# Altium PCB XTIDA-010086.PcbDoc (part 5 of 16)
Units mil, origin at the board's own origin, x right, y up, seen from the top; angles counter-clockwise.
Board outline 14763.78 x 8267.72 mil, 6 copper layers (Top Layer, GND Layer, Signal Layer 1, Signal Layer 2, Power Layer, Bottom Layer), stack 62 mil thick; 1933 components, 1002 nets, 4886 pads, 6482 vias.
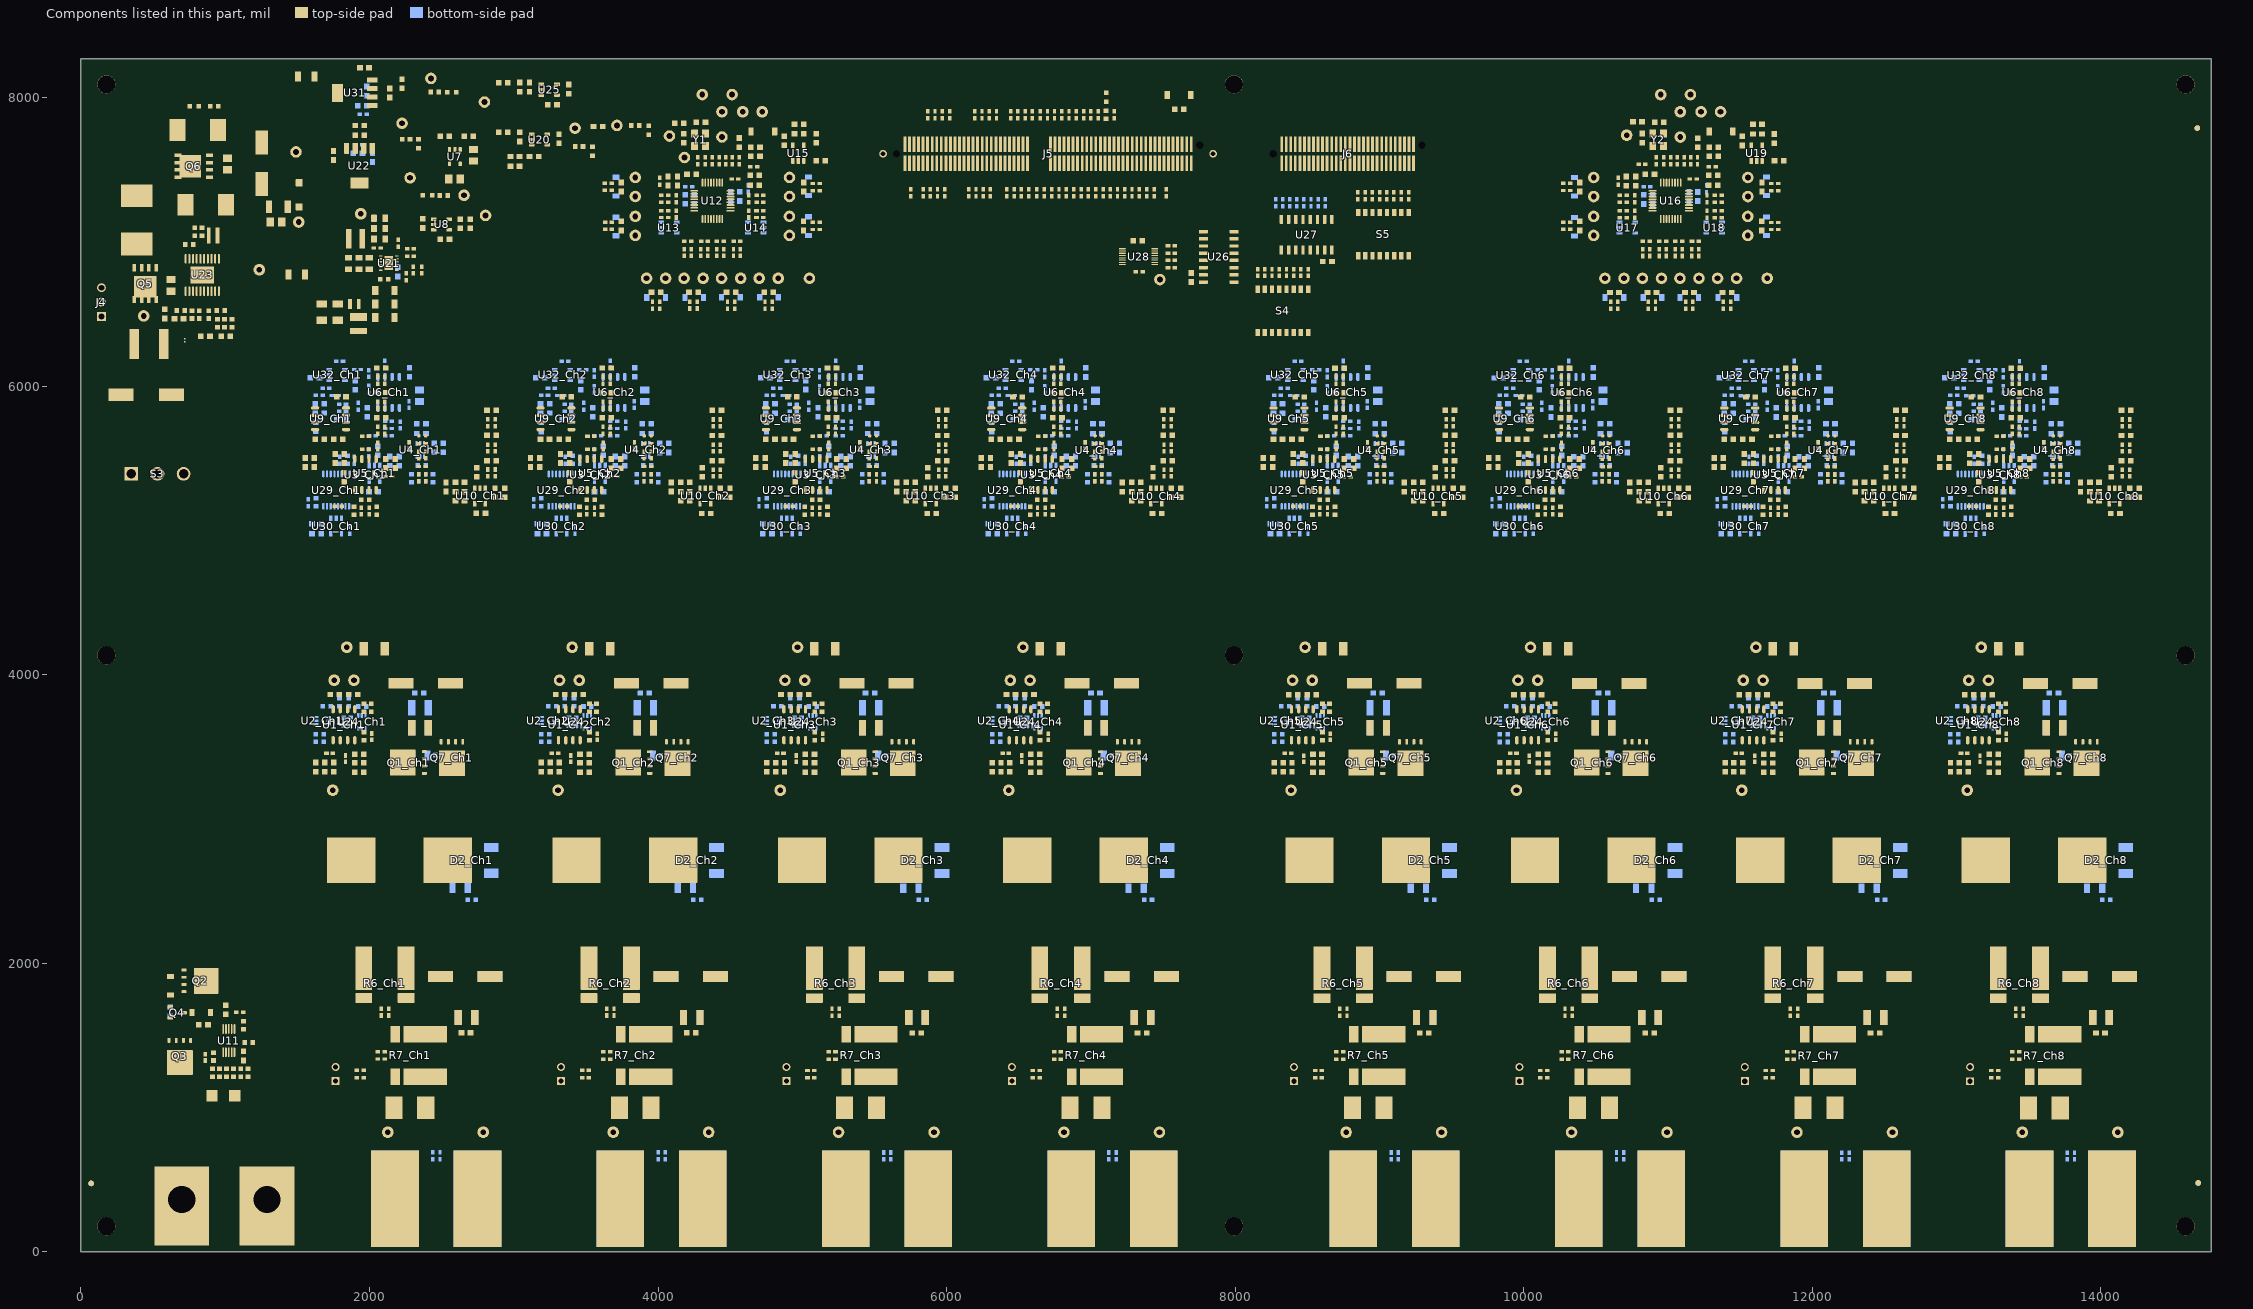
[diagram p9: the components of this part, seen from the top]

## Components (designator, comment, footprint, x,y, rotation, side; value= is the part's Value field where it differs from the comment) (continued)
U6_Ch7 "TLV2171IDR" D0008A_N 11898.7,5955.57 r90 bottom (schematic designator U6)
U6_Ch8 "TLV2171IDR" D0008A_N 13460.7,5955.5 r90 bottom (schematic designator U6)
U7 "LP5907MFX-2.5/NOPB" DBV0005A_L 2592,7589.32 r270 top
U8 "TPS72325DBVT" DBV0005A_N 2500,7119.7 r0 top
U9_Ch1 "LM393AD" D0008A_N 1731,5773.55 r180 top (schematic designator U9)
U9_Ch2 "LM393AD" D0008A_N 3293,5773.47 r180 top (schematic designator U9)
U9_Ch3 "LM393AD" D0008A_N 4855,5773.39 r180 top (schematic designator U9)
U9_Ch4 "LM393AD" D0008A_N 6417,5773.31 r180 top (schematic designator U9)
U9_Ch5 "LM393AD" D0008A_N 8372.7,5773.24 r180 top (schematic designator U9)
U9_Ch6 "LM393AD" D0008A_N 9934.7,5773.16 r180 top (schematic designator U9)
U9_Ch7 "LM393AD" D0008A_N 11496.7,5773.08 r180 top (schematic designator U9)
U9_Ch8 "LM393AD" D0008A_N 13058.7,5773 r180 top (schematic designator U9)
U10_Ch1 "TLV171IDBVR" DBV0005A_N 2766.54,5238.3 r270 top (schematic designator U10)
U10_Ch2 "TLV171IDBVR" DBV0005A_N 4328.54,5238.22 r270 top (schematic designator U10)
U10_Ch3 "TLV171IDBVR" DBV0005A_N 5890.54,5238.14 r270 top (schematic designator U10)
U10_Ch4 "TLV171IDBVR" DBV0005A_N 7452.54,5238.06 r270 top (schematic designator U10)
U10_Ch5 "TLV171IDBVR" DBV0005A_N 9408.24,5237.98 r270 top (schematic designator U10)
U10_Ch6 "TLV171IDBVR" DBV0005A_N 10970.24,5237.91 r270 top (schematic designator U10)
U10_Ch7 "TLV171IDBVR" DBV0005A_N 12532.24,5237.83 r270 top (schematic designator U10)
U10_Ch8 "TLV171IDBVR" DBV0005A_N 14094.24,5237.75 r270 top (schematic designator U10)
U11 "LM5060MM/NOPB" MUB10A_N 1025.33,1463.77 r90 top
U12 "ADS131M08IPBSR" PBS0032A_N 4377.11,7284.01 r90 top
U13 "ESDS304DBVR" DBV0005A_N 4076,7098.7 r0 bottom
U14 "ESDS304DBVR" DBV0005A_N 4677.29,7098.7 r180 bottom
U15 "REF2025DBV" DBV0005A_N 4972.33,7614.48 r90 top
U16 "ADS131M08IPBSR" PBS0032A_N 11018.82,7283.7 r90 top
U17 "ESDS304DBVR" DBV0005A_N 10717.7,7098.39 r0 bottom
U18 "ESDS304DBVR" DBV0005A_N 11318.99,7098.39 r180 bottom
U19 "REF2025DBV" DBV0005A_N 11614.03,7614.16 r90 top
U20 "LP5907MFX-3.3/NOPB" DBV0005A_N 3178.03,7708.4 r0 top
U21 "TPS63710DRR" DRR0012C 2134,6851.98 r180 top
U22 "LP38693MP-5.0/NOPB" NDC0005A_N 1931,7527.15 r270 top
U23 "LM5118MH/NOPB" MXA20A_N 841.5,6769.7 r90 top
U24_Ch1 "SN74LVC1G11DCKR" DCK0006A_N 1947.59,3673.33 r90 bottom (schematic designator U24)
U24_Ch2 "SN74LVC1G11DCKR" DCK0006A_N 3509.59,3673.25 r90 bottom (schematic designator U24)
U24_Ch3 "SN74LVC1G11DCKR" DCK0006A_N 5071.59,3673.17 r90 bottom (schematic designator U24)
U24_Ch4 "SN74LVC1G11DCKR" DCK0006A_N 6633.59,3673.09 r90 bottom (schematic designator U24)
U24_Ch5 "SN74LVC1G11DCKR" DCK0006A_N 8589.29,3673.01 r90 bottom (schematic designator U24)
U24_Ch6 "SN74LVC1G11DCKR" DCK0006A_N 10151.29,3672.93 r90 bottom (schematic designator U24)
U24_Ch7 "SN74LVC1G11DCKR" DCK0006A_N 11713.29,3672.86 r90 bottom (schematic designator U24)
U24_Ch8 "SN74LVC1G11DCKR" DCK0006A_N 13275.29,3672.78 r90 bottom (schematic designator U24)
U25 "TPS73633DBVR" DBV0005A_N 3245.53,8054 r0 top
U26 "SN74HC148DR" D0016A-MFG 7885.79,6895.7 r180 top
U27 "SN74HC148DR" D0016A-MFG 8495.2,7048.97 r270 top
U28 "SN74LV163ADGVR" DGV0016A_L 7330.2,6896.39 r0 top
U29_Ch1 "CD4053BPWR" PW0016A_L 1770,5279 r270 bottom (schematic designator U29)
U29_Ch2 "CD4053BPWR" PW0016A_L 3332,5278.92 r270 bottom (schematic designator U29)
U29_Ch3 "CD4053BPWR" PW0016A_L 4894,5278.84 r270 bottom (schematic designator U29)
U29_Ch4 "CD4053BPWR" PW0016A_L 6456,5278.76 r270 bottom (schematic designator U29)
U29_Ch5 "CD4053BPWR" PW0016A_L 8411.7,5278.69 r270 bottom (schematic designator U29)
U29_Ch6 "CD4053BPWR" PW0016A_L 9973.7,5278.61 r270 bottom (schematic designator U29)
U29_Ch7 "CD4053BPWR" PW0016A_L 11535.7,5278.53 r270 bottom (schematic designator U29)
U29_Ch8 "CD4053BPWR" PW0016A_L 13097.7,5278.45 r270 bottom (schematic designator U29)
U30_Ch1 "TLV1701AIDBVR" DBV0005A_N 1769,5030 r270 bottom (schematic designator U30)
U30_Ch2 "TLV1701AIDBVR" DBV0005A_N 3331,5029.92 r270 bottom (schematic designator U30)
U30_Ch3 "TLV1701AIDBVR" DBV0005A_N 4893,5029.84 r270 bottom (schematic designator U30)
U30_Ch4 "TLV1701AIDBVR" DBV0005A_N 6455,5029.76 r270 bottom (schematic designator U30)
U30_Ch5 "TLV1701AIDBVR" DBV0005A_N 8410.7,5029.69 r270 bottom (schematic designator U30)
U30_Ch6 "TLV1701AIDBVR" DBV0005A_N 9972.7,5029.61 r270 bottom (schematic designator U30)
U30_Ch7 "TLV1701AIDBVR" DBV0005A_N 11534.7,5029.53 r270 bottom (schematic designator U30)
U30_Ch8 "TLV1701AIDBVR" DBV0005A_N 13096.7,5029.45 r270 bottom (schematic designator U30)
U31 "LP38693MP-5.0/NOPB" NDC0005A_N 1899,8032 r180 top
U32_Ch1 "TLV171IDBVR" DBV0005A_N 1776,6077.24 r0 bottom (schematic designator U32)
U32_Ch2 "TLV171IDBVR" DBV0005A_N 3338.24,6076.91 r0 bottom (schematic designator U32)
U32_Ch3 "TLV171IDBVR" DBV0005A_N 4898.35,6077.31 r0 bottom (schematic designator U32)
U32_Ch4 "TLV171IDBVR" DBV0005A_N 6462.24,6076.76 r0 bottom (schematic designator U32)
U32_Ch5 "TLV171IDBVR" DBV0005A_N 8417.94,6076.68 r0 bottom (schematic designator U32)
U32_Ch6 "TLV171IDBVR" DBV0005A_N 9980.7,6075.84 r0 bottom (schematic designator U32)
U32_Ch7 "TLV171IDBVR" DBV0005A_N 11541.94,6076.52 r0 bottom (schematic designator U32)
U32_Ch8 "TLV171IDBVR" DBV0005A_N 13103.94,6076.44 r0 bottom (schematic designator U32)
Y1 "SIT8924BA-22-33E-8.192000G" SiTime_SiT8924B_2 4291.11,7706.01 r0 top
Y2 "SIT8924BA-22-33E-8.192000G" SiTime_SiT8924B_2 10931.82,7706.7 r0 top
ZZ1 "This Assembly Note is for PCB labels only" AssemblyNoteLabel 467,9160 r0 top
ZZ2 "These assemblies are ESD sensitive, ESD precautions shall be observed." AssemblyNote 468,9090 r0 top
ZZ3 "These assemblies must be clean and free from flux and all contaminants. Use of no clean flux is not acceptable." AssemblyNote 469,9025 r0 top
ZZ4 "These assemblies must comply with workmanship standards IPC-A-610 Class 2, unless otherwise specified." AssemblyNote 470,8958 r0 top

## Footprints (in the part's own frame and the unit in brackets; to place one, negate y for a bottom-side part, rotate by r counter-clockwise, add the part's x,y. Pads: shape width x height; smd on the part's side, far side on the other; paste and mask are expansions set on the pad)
0402 [mm] "0402 from SM-752 data"
  rect 0.8x0.6 smd: 1(-0.6,0) 2(0.6,0)
  silkscreen extent -1.22,-0.52 1.22,0.52, body extent -0.55,-0.3 0.55,0.3, height 0.6
0603 [mm] "0603 from SM-752 data"
  rect 1x0.95 smd: 1(-0.8,0) 2(0.8,0)
  silkscreen extent -1.52,-0.69 1.52,0.69, body extent -0.87,-0.47 0.87,0.47, height 1
0603_HV [mil] "Ernesto recommended land pattern.  26 mil between pads."
  rect 30x30 smd: 1(-28,0) 2(28,0)
  silkscreen extent -52,-24 52,24, body extent -34,-19 34,19, height 39
0603L [mm] "0603 from SM-752 data"
  rect 0.8x0.85 smd: 1(-0.7,0) 2(0.7,0)
  silkscreen extent -0.07,-0.33 0.07,0.33, body extent -0.87,-0.47 0.87,0.47, height 1
0612 [mm] "Panasonic recommended land pattern, fb97d03ed01.pdf dated April 2008"
  rect 0.65x2.75 smd: 1(-0.775,0) 2(0.775,0)
  silkscreen extent -1.1,-1.9 1.1,1.9, body extent -0.9,-1.7 0.9,1.7, height 0.85
0805_HV [mil] "0805 with 30mil clearance between pads"
  rect 50x63 smd: 1(-40,0) 2(40,0)
  silkscreen extent -74,-40 74,40, body extent -43,-29 43,29, height 57
0805_HV1 [mm] "Custom footprint based on analyzing multiple manufacturer recommendations"
  rrect10% 1x1.25 smd: 1(-1,0) 2(1,0)
  silkscreen extent -0.2,-0.75 0.2,0.75, body extent -1.1,-0.72 1.1,0.73, height 1.45
1206 [mm] "1206 from SM-752 data"
  rect 1.3x1.85 smd: 1(-1.45,0) 2(1.45,0)
  silkscreen extent -2.4,-1.21 2.4,1.21, body extent -1.7,-0.9 1.7,0.9, height 1.35
1206_190 [mm] "1206_190"
  rect 1.1x1.6 smd: 1(-1.7,0) 2(1.7,0)
  silkscreen extent -0.9,-1 0.9,1, body extent -1.75,-0.95 1.75,0.95, height 1.9
1206L [mm] "1206 from SM-752 data"
  rect 1.1x1.75 smd: 1(-1.35,0) 2(1.35,0)
  silkscreen extent -0.4,-0.77 0.4,0.77, body extent -1.7,-0.9 1.7,0.9, height 1.35
1210_270 [mm] "1210"
  rect 1.3x2.7 smd: 1(-1.45,0) 2(1.45,0)
  silkscreen extent -2.32,-1.57 2.32,1.57, body extent -1.7,-1.35 1.7,1.35, height 2.7
1210_280 [mm] "SMD, 2-Leads, Body 3.6x2.8mm, Height 2.8mm"
  rect 1.1x2.2 smd: 1(-1.65,0) 2(1.65,0)
  silkscreen extent -0.84,-1.4 0.84,1.4, body extent -1.8,-1.4 1.8,1.4, height 2.8
1806_HighSpeed [mm] "Wurth recommended land pattern"
  rrect8% 1.25x1.2 smd: 1(-2.125,0) 2(2.125,0)
  silkscreen extent -1.5,-1 1.5,1, body extent -2.25,-0.8 2.25,0.8, height 1.61
2220_250 [mm] "2220"
  rect 1.6x5.3 smd: 1(-2.6,0) 2(2.6,0)
  silkscreen extent -3.69,-2.94 3.69,2.94, body extent -2.95,-2.62 2.95,2.62, height 2.5
5108 [mm] "Keystone"
  rect 1.01x1.73 smd: 1(-1.445,0) 2(1.445,0)
  body extent -1.52,-0.85 1.52,0.85, height 0.71
6125FA [mm] "Cooper Bussman 6125FA Brick Fuses, recommended land pattern OC-2531 Rev. I 3/07"
  rect 3x4 smd: 1(-2.8,0) 2(2.8,0)
  silkscreen extent -4.57,-2.27 4.57,2.27, body extent -3.17,-1.42 3.17,1.41, height 2.84
AssemblyNote [mil] "Assembly Note"
AssemblyNoteLabel [mil] "Assembly Note for PCB Labels"
CAPSMT_62_F12 [mm] "F12, SMD, 2-Leads, Body 10.5x10.5mm, Height 12.7mm"
  rect 4.4x1.9 smd: 1(-4.35,0) 2(4.35,0)
  silkscreen extent -5.25,-5.25 5.25,5.25, body extent -5.25,-5.25 5.25,5.25, height 12.71
CAPSMT_62_HC0 [mm] "8 x 12mm:  Chemi-Con HC0"
  rect 4.2x2.2 smd: 1(-3.638,0.012) 2(3.662,0.012)
  silkscreen extent -4.24,-4.24 4.26,4.26, body extent -4.24,-4.24 4.26,4.26, height 12.5
CAPSMT_62_JA0 [mm] "10 x 10mm:  Chemi-Con JA0"
  rect 4.4x2.2 smd: 1(-4.45,0) 2(4.45,0)
  silkscreen extent -5.25,-5.25 5.25,5.25, body extent -5.25,-5.25 5.25,5.25, height 10.5
CB35-36-CY [mil] "Terminal 50A Lug"
  rect 550x380 hole 188 copper offset -45,0 paste-190: 1(0,0)
  body extent -960,-189 230,191, height 614
CE_Mark_5mm [mil] "Minimum text height for CE Mark"
  silkscreen extent -138,-98 138,98
controlCARD-120HSEC [mm] "Pads are not numbered according to Samtec datasheet."
  rect 0.5x2.724 smd: 1(-23.357,-1.678) 2(-23.357,1.722) 3(-22.557,-1.678) 4(-22.557,1.722) 5(-21.757,-1.678) 6(-21.757,1.722) 7(-20.957,-1.678) 8(-20.957,1.722) 9(-20.157,-1.678) 10(-20.157,1.722) 11(-19.357,-1.678) 12(-19.357,1.722) 13(-18.557,-1.678) 14(-18.557,1.722) 15(-17.757,-1.678) 16(-17.757,1.722) 17(-16.957,-1.678) 18(-16.957,1.722) 19(-16.157,-1.678) 20(-16.157,1.722) 21(-15.357,-1.678) 22(-15.357,1.722) 23(-14.557,-1.678) 24(-14.557,1.722) 25(-13.757,-1.678) 26(-13.757,1.722) 27(-12.957,-1.678) 28(-12.957,1.722) 29(-12.157,-1.678) 30(-12.157,1.722) 31(-11.357,-1.678) 32(-11.357,1.722) 33(-10.557,-1.678) 34(-10.557,1.722) 35(-9.757,-1.678) 36(-9.757,1.722) 37(-8.957,-1.678) 38(-8.957,1.722) 39(-8.157,-1.678) 40(-8.157,1.722) 41(-7.357,-1.678) 42(-7.357,1.722) 43(-6.557,-1.678) 44(-6.557,1.722) 45(-5.757,-1.678) 46(-5.757,1.722) 47(-4.957,-1.678) 48(-4.957,1.722) 49(-4.157,-1.678) 50(-4.157,1.722) 51(-3.357,-1.678) 52(-3.357,1.722) 53(-2.557,-1.678) 54(-2.557,1.722) 55(-1.757,-1.678) 56(-1.757,1.722) 57(2.243,-1.678) 58(2.243,1.722) 59(3.043,-1.678) 60(3.043,1.722) 61(3.843,-1.678) 62(3.843,1.722) 63(4.643,-1.678) 64(4.643,1.722) 65(5.443,-1.678) 66(5.443,1.722) 67(6.243,-1.678) 68(6.243,1.722) 69(7.043,-1.678) 70(7.043,1.722) 71(7.843,-1.678) 72(7.843,1.722) 73(8.643,-1.678) 74(8.643,1.722) 75(9.443,-1.678) 76(9.443,1.722) 77(10.243,-1.678) 78(10.243,1.722) 79(11.043,-1.678) 80(11.043,1.722) 81(11.843,-1.678) 82(11.843,1.722) 83(12.643,-1.678) 84(12.643,1.722) 85(13.443,-1.678) 86(13.443,1.722) 87(14.243,-1.678) 88(14.243,1.722) 89(15.043,-1.678) 90(15.043,1.722) 91(15.843,-1.678) 92(15.843,1.722) 93(16.643,-1.678) 94(16.643,1.722) 95(17.443,-1.678) 96(17.443,1.722) 97(18.243,-1.678) 98(18.243,1.722) 99(19.043,-1.678) 100(19.043,1.722) 101(19.843,-1.678) 102(19.843,1.722) 103(20.643,-1.678) 104(20.643,1.722) 105(21.443,-1.678) 106(21.443,1.722) 107(22.243,-1.678) 108(22.243,1.722) 109(23.043,-1.678) 110(23.043,1.722) 111(23.843,-1.678) 112(23.843,1.722) 113(24.643,-1.678) 114(24.643,1.722) 115(25.443,-1.678) 116(25.443,1.722) 117(26.243,-1.678) 118(26.243,1.722) 119(27.043,-1.678) 120(27.043,1.722)
  round 0.025 hole 1.27 unplated mask+0.876: 181(-24.857,0.022) 182(28.543,1.522)
  round 1.348 hole 0.84: 185(-27.207,0.022) 186(30.893,0.022)
  silkscreen extent -32.11,-3.86 35.8,3.9, body extent -31.75,-3.48 35.3,3.52, height 12.35
controlCARD-180HSEC-60pinAddon [mm] "Pads are not numbered according to datasheet."
  round 0.025 hole 1.27 unplated mask+0.876: 61(-13.1,0) 62(13.1,1.5)
  rect 0.5x2.724 smd: 121(-11.6,-1.7) 122(-11.6,1.7) 123(-10.8,-1.7) 124(-10.8,1.7) 125(-10,-1.7) 126(-10,1.7) 127(-9.2,-1.7) 128(-9.2,1.7) 129(-8.4,-1.7) 130(-8.4,1.7) 131(-7.6,-1.7) 132(-7.6,1.7) 133(-6.8,-1.7) 134(-6.8,1.7) 135(-6,-1.7) 136(-6,1.7) 137(-5.2,-1.7) 138(-5.2,1.7) 139(-4.4,-1.7) 140(-4.4,1.7) 141(-3.6,-1.7) 142(-3.6,1.7) 143(-2.8,-1.7) 144(-2.8,1.7) 145(-2,-1.7) 146(-2,1.7) 147(-1.2,-1.7) 148(-1.2,1.7) 149(-0.4,-1.7) 150(-0.4,1.7) 151(0.4,-1.7) 152(0.4,1.7) 153(1.2,-1.7) 154(1.2,1.7) 155(2,-1.7) 156(2,1.7) 157(2.8,-1.7) 158(2.8,1.7) 159(3.6,-1.7) 160(3.6,1.7) 161(4.4,-1.7) 162(4.4,1.7) 163(5.2,-1.7) 164(5.2,1.7) 165(6,-1.7) 166(6,1.7) 167(6.8,-1.7) 168(6.8,1.7) 169(7.6,-1.7) 170(7.6,1.7) 171(8.4,-1.7) 172(8.4,1.7) 173(9.2,-1.7) 174(9.2,1.7) 175(10,-1.7) 176(10,1.7) 177(10.8,-1.7) 178(10.8,1.7) 179(11.6,-1.7) 180(11.6,1.7)
  silkscreen extent -14.68,-3.88 14.68,3.88, body extent -14.3,-3.5 14.3,3.5, height 7.95
CSM3637Z [mm] "SMD, 4-Leads, Body 9.398x9.144mm"
  rrect3% 7.62x2.95 smd: 1(-1.145,3.735) 2(-1.145,-3.735)
  rrect6% 1.68x2.95 smd: 3(4.115,3.735) 4(4.115,-3.735)
  silkscreen extent -4.83,-1.9 4.83,1.9, body extent -4.83,-4.7 4.83,4.7, height 0.89
D0008A_N [mm] "SOIC, 8-Leads, Body 4.9x3.9mm, Pitch 1.27mm, IPC Medium Density"
  oval 1.45x0.6 smd: 1(-2.725,1.905) 2(-2.725,0.635) 3(-2.725,-0.635) 4(-2.725,-1.905) 5(2.725,-1.905) 6(2.725,-0.635) 7(2.725,0.635) 8(2.725,1.905)
  silkscreen extent -3.3,-2.5 0.9,2.5, body extent -3,-2.45 3,2.45, height 1.63
D0016A-MFG [mm]
  rrect17% 1.55x0.6 smd paste-1000 mask+0: 1(-2.7,4.445) 2(-2.7,3.175) 3(-2.7,1.905) 4(-2.7,0.635) 5(-2.7,-0.635) 6(-2.7,-1.905) 7(-2.7,-3.175) 8(-2.7,-4.445) 9(2.7,-4.445) 10(2.7,-3.175) 11(2.7,-1.905) 12(2.7,-0.635) 13(2.7,0.635) 14(2.7,1.905) 15(2.7,3.175) 16(2.7,4.445)
  silkscreen extent -4.18,-5 1.55,5, body extent -3,-4.95 3,4.95, height 1.75
DBV0005A_L [mm] "SOT23, 5-Leads, Body 2.9x1.6mm, Pitch 0.95mm, Lead Span 2.8mm, IPC High Density"
  rrect18% 0.8x0.55 smd: 1(-1.275,0.95) 2(-1.275,0) 3(-1.275,-0.95) 4(1.275,-0.95) 5(1.275,0.95)
  silkscreen extent -0.35,-1.55 0.35,1.55, body extent -1.42,-1.46 1.42,1.46, height 1.09
DBV0005A_N [mm] "SOT23, 5-Leads, Body 2.9x1.6mm, Pitch 0.95mm, Lead Span 2.8mm, IPC Medium Density"
  rrect17% 1x0.6 smd: 1(-1.375,0.95) 2(-1.375,0) 3(-1.375,-0.95) 4(1.375,-0.95) 5(1.375,0.95)
  silkscreen extent -0.25,-1.55 0.25,1.55, body extent -1.42,-1.46 1.42,1.46, height 1.09
DCK0006A_N [mm] "SOT23, 6-Leads, Body 2x1.3mm, Pitch 0.65mm, Lead Span 2.1mm, IPC Medium Density"
  rrect25% 0.85x0.4 smd: 1(-1.125,0.65) 2(-1.125,0) 3(-1.125,-0.65) 4(1.125,-0.65) 5(1.125,0) 6(1.125,0.65)
  silkscreen extent -1.5,-1.09 0.51,1.09, body extent -1.14,-1 1.14,1, height 0.95
DGV0016A_L [mm] "TSSOP, 16-Leads, Body 3.6x4.4mm, Pitch 0.4mm, IPC High Density"
  oval 1.2x0.2 smd: 1(-2.85,1.4) 2(-2.85,1) 3(-2.85,0.6) 4(-2.85,0.2) 5(-2.85,-0.2) 6(-2.85,-0.6) 7(-2.85,-1) 8(-2.85,-1.4) 9(2.85,-1.4) 10(2.85,-1) 11(2.85,-0.6) 12(2.85,-0.2) 13(2.85,0.2) 14(2.85,0.6) 15(2.85,1) 16(2.85,1.4)
  silkscreen extent -3.32,-1.85 1.85,1.85, body extent -3.21,-1.8 3.21,1.8, height 1.2
DNK0008A [mm] "SON, 8-Leads, Body 5x6mm"
  rrect39% 0.86x0.51 smd paste-0.05 mask-0.05: 1(-2.82,1.905) 2(-2.82,0.635) 3(-2.82,-0.635) 4(-2.82,-1.905) 5(2.82,-1.905) 6(2.82,-0.635) 7(2.82,0.635) 8(2.82,1.905)
  rrect8% 1.48x1.27 on Top Paste: 9(-0.18,-1.47) 9(-0.18,0) 9(-0.18,1.47) 9(1.5,-1.47) 9(1.5,0) 9(1.5,1.47)
  rrect5% 4.34x4.6 smd paste-3 mask-0.05: 9(1.08,0)
  silkscreen extent -3.2,-2.7 3.2,2.7, body extent -3.05,-2.55 3.05,2.55, height 1.06
DPAK [mm] "D-PAK, 3-Pads, Body 6.22x6.73mm (max), TO-252AA using nominal STEP model"
  rrect6% 2.6x1.6 smd: 1(-3.4,2.28) 3(-3.4,-2.28)
  rrect2% 6.2x5.8 smd paste-2.9: 4(3.4,0)
  silkscreen extent -4.5,-3.3 4.7,3.28, body extent -3.86,-3.29 5.84,3.29, height 2.48
DQJ0008A [mm] "SMD, 8-Leads, Body 5.75x4.9mm"
  rrect39% 0.91x0.51 smd paste-0.05 mask-0.05: 1(-2.795,1.905) 2(-2.795,0.635) 3(-2.795,-0.635) 4(-2.795,-1.905) 5(2.795,-1.905) 6(2.795,-0.635) 7(2.795,0.635) 8(2.795,1.905)
  rrect8% 1.58x1.25 on Top Paste: 9(-0.38,1.45) 9(-0.38,0) 9(-0.38,-1.45) 9(1.4,1.45) 9(1.4,0) 9(1.4,-1.45)
  rrect3% 3.48x4.47 on Top Solder: 9(0.55,0)
  rrect2% 4.49x4.57 smd paste-2.5 mask-2.5: 9(1.005,0)
  silkscreen extent -3,-2.6 3,2.6, body extent -3.13,-2.45 3.13,2.45, height 1.15
DRR0012C [mm] "SON, 12-Leads, Body 3x3mm, Pitch 0.5mm, Thermal Pad 1.5x2.5mm"
  rrect40% 0.6x0.25 smd: 1(-1.4,1.25) 2(-1.4,0.75) 3(-1.4,0.25) 4(-1.4,-0.25) 5(-1.4,-0.75) 6(-1.4,-1.25) 7(1.4,-1.25) 8(1.4,-0.75) 9(1.4,-0.25) 10(1.4,0.25) 11(1.4,0.75) 12(1.4,1.25)
  rrect9% 1.38x1.11 on Top Paste: 13(0,0.66) 13(0,-0.66)
  rrect7% 1.5x2.5 smd paste-1.7: 13(0,0)
  silkscreen extent -1.6,-1.65 1.6,1.65, body extent -1.55,-1.55 1.55,1.55, height 0.81
ESD_Overlay_Medium [mil]
  silkscreen extent -127,-109 125,110
F95_B [mm] "AVX F95 series, size B"
  rect 1.4x3 smd: 1(-1.25,0)
  rect 1.1x3 smd: 2(1.2,0)
  silkscreen extent -0.33,-1.73 1.25,1.73, body extent -2.03,-1.5 1.67,1.5, height 2
FCC_disclaimer [mil]
Fiducial10-20 [mm]
  round 1 smd mask+0.5: 1(0,0)
  Top Layer keep-out circle w1.178: c0,0 r0.5
FP-CB25-18-CY_CONN_TERM_LUG_25MM4_7MM9-MFG [mil]
  rrect1% 670x330 smd paste+0 mask+0: 1(175,0)
  rrect1% 670x330 smd far side paste-39370.1 mask+0: 1(175,0)
  silkscreen extent 0,-180 525,180, body extent -164,-169 514,169, height 10
IEC_HotSurface_Small [mil]
  silkscreen extent -107,-93 107,92
JST_B2B-EH-A [mm] "Header (Shrouded), 2.5mm, 2x1, TH"
  rect 1.4x1.4 hole 0.9: 1(-1.25,0)
  round 1.4 hole 0.9: 2(1.25,0)
  silkscreen extent -4.2,-2.2 3.75,1.6, body extent -3.75,-2.2 3.75,1.6, height 6
Keystone5000 [mil] "For Keystone 500x miniature loop terminals"
  round 80 hole 40: 1(0,0)
  silkscreen extent -52,-52 52,52, body extent -49,-49 49,49, height 182
Keystone5001 [mil] "For Keystone 500x miniature loop terminals"
  round 80 hole 40: 1(0,0)
  silkscreen extent -52,-52 52,52, body extent -49,-49 49,49, height 182
Keystone5002 [mil] "For Keystone 500x miniature loop terminals"
  round 80 hole 40: 1(0,0)
  silkscreen extent -52,-52 52,52, body extent -49,-49 49,49, height 182
KEYSTONE_2205 [mil] "THREAD HEX ALUMINUM STANDOFF 4-40, F-F 1\""
  round 1 on Mech4: 0(0,0)
  body extent -148,-128 148,128, height 1001
Label_650x200 [mil] "Thermal Transfer Label"
  round 1 on Mech13: 0(0,0)
  silkscreen extent -325,-100 325,100, body extent -325,-100 325,100, height 1
MAKK2016 [mm] "Taiyo Yuden"
  rect 0.7x1.8 smd: 1(-0.75,0) 2(0.75,0)
  body extent -1.05,-0.85 1.05,0.85, height 1
Molex_0022284033 [mm] "Header, 2.54mm, 3x1, TH"
  rect 1.55x1.55 hole 1.02: 1(-2.54,0)
  round 1.55 hole 1.02: 2(0,0) 3(2.54,0)
  silkscreen extent -3.81,-1.24 3.81,1.5, body extent -3.81,-1.24 3.81,1.24, height 8.4
mss1278 [mm] "Coilcraft recommended land pattern.  Document 598-2 rev 04/04/13"
  rect 4x5.5 smd: 1(-4.25,0) 2(4.25,0)
  silkscreen extent -6.2,-6.2 6.2,6.2, body extent -6.15,-6.15 6.15,6.15, height 8.05
MUB10A_N [mm] "TSSOP, 10-Leads, Body 3x3mm, Pitch 0.5mm, IPC Medium Density"
  oval 1.7x0.3 smd: 1(-2.05,1) 2(-2.05,0.5) 3(-2.05,0) 4(-2.05,-0.5) 5(-2.05,-1) 6(2.05,-1) 7(2.05,-0.5) 8(2.05,0) 9(2.05,0.5) 10(2.05,1)
  silkscreen extent -2.17,-1.6 0.8,1.82, body extent -1.6,-1.6 1.6,1.6, height 1.09
MXA20A_N [mm] "TSOP, 20-Leads, Body 6.5x4.4mm, Pitch 0.65mm, Exposed Pad, IPC Medium Density"
  oval 1.7x0.35 smd: 1(-2.85,2.925) 2(-2.85,2.275) 3(-2.85,1.625) 4(-2.85,0.975) 5(-2.85,0.325) 6(-2.85,-0.325) 7(-2.85,-0.975) 8(-2.85,-1.625) 9(-2.85,-2.275) 10(-2.85,-2.925) 11(2.85,-2.925) 12(2.85,-2.275) 13(2.85,-1.625) 14(2.85,-0.975) 15(2.85,-0.325) 16(2.85,0.325) 17(2.85,0.975) 18(2.85,1.625) 19(2.85,2.275) 20(2.85,2.925)
  rect 3x4.2 smd: 21(0,0)
  silkscreen extent -2.97,-3.3 1.6,3.77, body extent -2.25,-3.3 2.25,3.3, height 1.1
NDC0005A_N [mm] "SOT223, 5-Leads, Body 6.7x3.71mm, Pitch 1.5mm, IPC Medium Density"
  rrect11% 1.9x0.9 smd: 1(-3.05,2.25) 2(-3.05,0.75) 3(-3.05,-0.75) 4(-3.05,-2.25)
  rrect5% 1.9x3.2 smd: 5(3.05,0)
  silkscreen extent -3.17,-3.35 1.8,3.38, body extent -3.48,-3.25 3.48,3.25, height 1.7
Net-Tie_10mil [mil] "10mil net tie, no solder mask opening, no solder paste"
  rect 10x10 smd paste-5 mask-5: 1(-10,0) 2(10,0)
  Top Layer region: -6,5 6,5 6,-5 -6,-5
"NY PMS 440 0025 PH"#1 [mm] "4-40 nylon screw and mounting hole"
  round 3.2 hole 3.2 unplated mask+0.178: 1(0,0)
  body extent -3.3,-3.3 3.3,3.3, height 2.69
"NY PMS 440 0025 PH"#2 [mm] "4-40 nylon screw and mounting hole"
  round 3.2 hole 3.2 unplated paste+0 mask+0.178: 1(0,0)
  body extent -3.3,-3.3 3.3,3.3, height 2.69
Pb-Free_Overlay_Small [mil]
  silkscreen extent -46,-46 46,46
PBS0032A_N [mm]
  oval 1.4x0.3 smd: 1(-3.2,1.75) 2(-3.2,1.25) 3(-3.2,0.75) 4(-3.2,0.25) 5(-3.2,-0.25) 6(-3.2,-0.75) 7(-3.2,-1.25) 8(-3.2,-1.75) 17(3.2,-1.75) 18(3.2,-1.25) 19(3.2,-0.75) 20(3.2,-0.25) 21(3.2,0.25) 22(3.2,0.75) 23(3.2,1.25) 24(3.2,1.75)
  oval 0.3x1.4 smd: 9(-1.75,-3.2) 10(-1.25,-3.2) 11(-0.75,-3.2) 12(-0.25,-3.2) 13(0.25,-3.2) 14(0.75,-3.2) 15(1.25,-3.2) 16(1.75,-3.2) 25(1.75,3.2) 26(1.25,3.2) 27(0.75,3.2) 28(0.25,3.2) 29(-0.25,3.2) 30(-0.75,3.2) 31(-1.25,3.2) 32(-1.75,3.2)
  silkscreen extent -3.6,-2.53 2.53,2.53, body extent -3.5,-3.5 3.5,3.5, height 1.12
PowerPAK_SO-8 [mil] "Vishay PowerPAK SO-8, Body 5.3x6.0mm (max), Pitch 1.27mm, IPC Medium Density"
  rect 50x24 smd mask+2.99: 1(-109.5,75) 2(-109.5,25) 3(-109.5,-25) 4(-109.5,-75)
  rect 48x24 smd mask+2.99: 5(109.5,-75) 8(109.5,75)
  rect 48x24 smd paste-12 mask+2.99: 6(109.5,-25) 7(109.5,25)
  rect 150x154 smd paste-75 mask+2.99: 9(22.5,0)
  silkscreen extent -130,-104 59,104, body extent -121,-102 121,102, height 43
PW0016A_L [mm] "TSOP, 16-Leads, Body 5x4.4mm, Pitch 0.65mm, IPC High Density"
  oval 1.2x0.4 smd: 1(-2.85,2.275) 2(-2.85,1.625) 3(-2.85,0.975) 4(-2.85,0.325) 5(-2.85,-0.325) 6(-2.85,-0.975) 7(-2.85,-1.625) 8(-2.85,-2.275) 9(2.85,-2.275) 10(2.85,-1.625) 11(2.85,-0.975) 12(2.85,-0.325) 13(2.85,0.325) 14(2.85,0.975) 15(2.85,1.625) 16(2.85,2.275)
  silkscreen extent -2,-2.55 1.85,2.55, body extent -3.21,-2.5 3.21,2.5, height 1
SiTime_SiT8924B_2 [mm] "SMD, 4-Leads, Body 3.2x2.5mm"
  rrect8% 1.2x1.4 smd: 1(-0.95,1.1) 2(-0.95,-1.1) 3(0.95,-1.1) 4(0.95,1.1)
  body extent -1.27,-1.62 1.27,1.62, height 0.8
SM_RADIAL_10AMM [mm] "10 x 7.9mm:  Sanyo Oscon F8"
  rect 4.4x1.9 smd: 1(-4.35,0) 2(4.35,0)
  silkscreen extent -5.25,-5.25 5.25,5.25, body extent -5.25,-5.25 5.25,5.25, height 8
SMA [mm] "Molded Diode, 2-Leads, Body 4.3x2.6mm, IPC Medium Density, based on OnSemi component dimensions and land pattern"
  rect 2x2 smd: 1(-2,0) 2(2,0)
  silkscreen extent -3.66,-1.57 2.79,1.57, body extent -2.6,-1.3 2.6,1.3, height 2.42
SMC [mil] "Molded Diode, 2-Leads, Body 6.9x5.8mm, IPC Medium Density, based on OnSemi component dimensions and land patterns"
  rect 110x150 smd: 1(-140.49,0) 2(140.49,0)
  silkscreen extent -221,-124 189,123, body extent -156,-116 156,116, height 91
SOD-123 [mm] "On Semi recommended land pattern"
  rect 0.915x1.22 smd: 1(-1.637,0) 2(1.637,0)
  silkscreen extent -2.74,-1.17 2.03,1.17, body extent -1.93,-0.9 1.93,0.9, height 1.35
SOD-523 [mm] "NXP Semiconductor recommended land pattern, nominal STEP model"
  rect 0.8x0.6 smd paste-0.05: 1(-0.55,0) 2(0.55,0)
  silkscreen extent -1.65,-0.66 1.2,0.66, body extent -0.8,-0.4 0.8,0.4, height 0.72
SOT-23 [mm] "SOT23, 3-Leads, Body 2.9x1.3mm, Pitch 0.95mm, Lead Span 2.5mm, IPC Medium Density"
  rrect50% 1x0.6 smd: 1(-1.2,0.95) 2(-1.2,-0.95) 3(1.2,0)
  silkscreen extent -1.62,-1.5 0.7,1.5, body extent -1.16,-1.45 1.21,1.45, height 1
SW_218-8LP [mm] "SMD, 16-Leads, Body 11.33x5.8mm, Pitch 1.27mm"
  rect 1.27x0.76 smd: 1(-3.81,4.445) 2(-3.81,3.175) 3(-3.81,1.905) 4(-3.81,0.635) 5(-3.81,-0.635) 6(-3.81,-1.905) 7(-3.81,-3.175) 8(-3.81,-4.445) 9(3.81,-4.445) 10(3.81,-3.175) 11(3.81,-1.905) 12(3.81,-0.635) 13(3.81,0.635) 14(3.81,1.905) 15(3.81,3.175) 16(3.81,4.445)
  silkscreen extent -2.9,-5.67 2.9,5.9, body extent -4.22,-5.66 4.22,5.66, height 2.62
"SW_ L101011MS02Q" [mm] "SWITCH SLIDE sPST 4A PCB"
  rect 2.416x2.416 hole 1.65: 1(2.857,4.6)
  round 2.416 hole 1.65: 2(2.857,0) 3(2.858,-4.6)
  silkscreen extent -5.4,-9.55 5.4,9.55, body extent -5.39,-9.55 5.39,9.55, height 14.18
SW_TL1015AF160QG [mm] "E-Switch"
  rrect11% 0.95x1.4 smd: 1(-2.075,0) 2(2.075,0)
  body extent -2.3,-1.5 2.3,1.5, height 2
TP_25MIL-SMT [mil]
  round 25 smd mask-2.5: 1(0,0)
"WE-HCF ROUND_2920" [mm] "SMT High Current Inductor, 2-Leads, body 28x25mm"
  rrect1% 8.5x8 smd: 1(-8.5,0) 2(8.5,0)
  silkscreen extent -11.35,-13.65 11.35,13.65, body extent -11.55,-13.65 11.55,13.65, height 20
WE-LHMI_4020 [mm] "WERTH"
  rrect7% 1.5x2.4 smd: 1(-1.85,0) 2(1.85,0)
  silkscreen extent -2.2,-2.2 2.2,2.2, body extent -2.15,-2.15 2.15,2.15, height 2
WEEE_Minimum [mil] "WEEElie bin"
  silkscreen extent -95,-172 99,104
WL-SMCW_GREEN [mm] "WURTH"
  rect 0.8x0.8 smd: 1(-0.8,0) 2(0.8,0)
  silkscreen extent -1.9,-0.8 1.2,0.8, body extent -0.85,-0.45 0.85,0.45, height 0.8
Wurth_60900213421 [mil] "Shunt, 2.54mm, Black"
  round 1 on Mech3: 0(0,0)
  body extent -98,-48 98,48, height 236
XFL4020 [mm] "Coilcraft XFL4020 7/18/12"
  rect 0.98x3.4 smd: 1(-1.181,0) 2(1.181,0)
  silkscreen extent -2.16,-2.16 2.16,2.16, body extent -2.15,-2.15 2.15,2.15, height 2.1

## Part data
C1_Ch1 C1_Ch2 C1_Ch3 C1_Ch4 C1_Ch5 C1_Ch6 C1_Ch7 C1_Ch8 C14_Ch1 C14_Ch2 C14_Ch3 C14_Ch4 C14_Ch5 C14_Ch6 C14_Ch7 C14_Ch8 C56 C122_Ch1 C122_Ch2 C122_Ch3 C122_Ch4 C122_Ch5 C122_Ch6 C122_Ch7 C122_Ch8 C135_Ch1 C135_Ch2 C135_Ch3 C135_Ch4 C135_Ch5 C135_Ch6 C135_Ch7 C135_Ch8 C151_Ch1 C151_Ch2 C151_Ch3 C151_Ch4 C151_Ch5 C151_Ch6 C151_Ch7 C151_Ch8: "CAP, CERM, 0.1 µF, 25 V, +/- 5%, X7R, 0603", Cap_Case=0603, Manufacturer=Kemet, Supplier Part Number 1=399-1282-1-ND, TempCo=X7R, Tolerance_%=5, Value1=Unknown, Value2=25V, ValueDisplayed=0.1µF
C2_Ch1 C2_Ch2 C2_Ch3 C2_Ch4 C2_Ch5 C2_Ch6 C2_Ch7 C2_Ch8: "CAP, CERM, 100 pF, 50 V, +/- 5%, C0G/NP0, 0603", Cap_Case=0603, Manufacturer=MuRata, Supplier Part Number 1=490-1427-1-ND, TempCo=C0G/NP0, Tolerance_%=5, Value1=Unknown, Value2=50V, ValueDisplayed=DNP
C3_Ch1 C3_Ch2 C3_Ch3 C3_Ch4 C3_Ch5 C3_Ch6 C3_Ch7 C3_Ch8: library part 25SVPF330M, "330µF 35V Aluminum Polymer Capacitor Radial, Can - SMD 18mOhm 1000 Hrs @ 125°C", Cap_Case=F12, Manufacturer=Panasonic, Supplier Part Number 1=P122136TR-ND, Tolerance_%=20, Value1="0.014 ohm", Value2=35V, ValueDisplayed=330µF
C4_Ch1 C4_Ch2 C4_Ch3 C4_Ch4 C4_Ch5 C4_Ch6 C4_Ch7 C4_Ch8 C5_Ch1 C5_Ch2 C5_Ch3 C5_Ch4 C5_Ch5 C5_Ch6 C5_Ch7 C5_Ch8 C6_Ch1 C6_Ch2 C6_Ch3 C6_Ch4 C6_Ch5 C6_Ch6 C6_Ch7 C6_Ch8: "CAP, CERM, 22 µF, 25 V, +/- 10%, X7R, 1210", Cap_Case=1210, Manufacturer=MuRata, Supplier Part Number 1=490-5313-1-ND, TempCo=X7R, Tolerance_%=10, Value1=Unknown, Value2=25V, ValueDisplayed=22µF
C7_Ch1 C7_Ch2 C7_Ch3 C7_Ch4 C7_Ch5 C7_Ch6 C7_Ch7 C7_Ch8 C11_Ch1 C11_Ch2 C11_Ch3 C11_Ch4 C11_Ch5 C11_Ch6 C11_Ch7 C11_Ch8 C20_Ch1 C20_Ch2 C20_Ch3 C20_Ch4 C20_Ch5 C20_Ch6 C20_Ch7 C20_Ch8 C23_Ch1 C23_Ch2 C23_Ch3 C23_Ch4 C23_Ch5 C23_Ch6 C23_Ch7 C23_Ch8 C29_Ch1 C29_Ch2 C29_Ch3 C29_Ch4 C29_Ch5 C29_Ch6 C29_Ch7 C29_Ch8 C30_Ch1 C30_Ch2 C30_Ch3 C30_Ch4 C30_Ch5 C30_Ch6 C30_Ch7 C30_Ch8 C33_Ch1 C33_Ch2 C33_Ch3 C33_Ch4 C33_Ch5 C33_Ch6 C33_Ch7 C33_Ch8 C34_Ch1 C34_Ch2 C34_Ch3 C34_Ch4 C34_Ch5 C34_Ch6 C34_Ch7 C34_Ch8 C40_Ch1 C40_Ch2 C40_Ch3 C40_Ch4 C40_Ch5 C40_Ch6 C40_Ch7 C40_Ch8 C43_Ch1 C43_Ch2 C43_Ch3 C43_Ch4 C43_Ch5 C43_Ch6 C43_Ch7 C43_Ch8 C44_Ch1 C44_Ch2 C44_Ch3 C44_Ch4 C44_Ch5 C44_Ch6 C44_Ch7 C44_Ch8 C45_Ch1 C45_Ch2 C45_Ch3 C45_Ch4 C45_Ch5 C45_Ch6 C45_Ch7 C45_Ch8 C47_Ch1 C47_Ch2 C47_Ch3 C47_Ch4 C47_Ch5 C47_Ch6 C47_Ch7 C47_Ch8 C53_Ch1 C53_Ch2 C53_Ch3 C53_Ch4 C53_Ch5 C53_Ch6 C53_Ch7 C53_Ch8 C62 C64 C70 C73 C76 C77 C80 C83 C85 C91 C94 C97 C98 C101 C123 C127 C128 C136_Ch1 C136_Ch2 C136_Ch3 C136_Ch4 C136_Ch5 C136_Ch6 C136_Ch7 C136_Ch8 C138 C142 C143 C144 C145 C146 C147 C148 C149 C150_Ch1 C150_Ch2 C150_Ch3 C150_Ch4 C150_Ch5 C150_Ch6 C150_Ch7 C150_Ch8 C166_Ch1 C166_Ch2 C166_Ch3 C166_Ch4 C166_Ch5 C166_Ch6 C166_Ch7 C166_Ch8 C167_Ch1 C167_Ch2 C167_Ch3 C167_Ch4 C167_Ch5 C167_Ch6 C167_Ch7 C167_Ch8: library part CMP-0006752-5, "CAP, CERM, 0.1 uF, 25 V, +/- 5%, X7R, 0603", Cap_Case=0603, Manufacturer=AVX, PartNumber=06033C104JAT2A, Supplier Part Number 1=478-3713-1-ND, TempCo=X7R, Tolerance_%=5%, Value1="0.05 ohm", Value2=25V, ValueDisplayed=0.1uF
C8_Ch1 C8_Ch2 C8_Ch3 C8_Ch4 C8_Ch5 C8_Ch6 C8_Ch7 C8_Ch8 C58: "CAP, CERM, 1 µF, 25 V, +/- 10%, X7R, 0603", Cap_Case=0603, Manufacturer=Kemet, Supplier Part Number 1=399-7376-1-ND, TempCo=X7R, Tolerance_%=10, Value1=Unknown, Value2=25V, ValueDisplayed=1µF
C9_Ch1 C9_Ch2 C9_Ch3 C9_Ch4 C9_Ch5 C9_Ch6 C9_Ch7 C9_Ch8 C10_Ch1 C10_Ch2 C10_Ch3 C10_Ch4 C10_Ch5 C10_Ch6 C10_Ch7 C10_Ch8: library part 10SVP560M, "560µF 20V Aluminum Polymer Capacitor Radial, Can - SMD 12mOhm 1000 Hrs @ 125°C", Cap_Case=10.3x10.3x12.6, Manufacturer=Panasonic, Supplier Part Number 1=P122119TR-ND, Tolerance_%=20, Value1="0.013 ohm", Value2=20V, ValueDisplayed=560µF
C12_Ch1 C12_Ch2 C12_Ch3 C12_Ch4 C12_Ch5 C12_Ch6 C12_Ch7 C12_Ch8 C13_Ch1 C13_Ch2 C13_Ch3 C13_Ch4 C13_Ch5 C13_Ch6 C13_Ch7 C13_Ch8: "CAP, CERM, 47 µF, 10 V, +/- 20%, X7R, 1210", Cap_Case=1210, Manufacturer=MuRata, Supplier Part Number 1=490-6543-1-ND, TempCo=X7R, Tolerance_%=20, Value1=Unknown, Value2=10V, ValueDisplayed=47µF
C15_Ch1 C15_Ch2 C15_Ch3 C15_Ch4 C15_Ch5 C15_Ch6 C15_Ch7 C15_Ch8 C21_Ch1 C21_Ch2 C21_Ch3 C21_Ch4 C21_Ch5 C21_Ch6 C21_Ch7 C21_Ch8 C22_Ch1 C22_Ch2 C22_Ch3 C22_Ch4 C22_Ch5 C22_Ch6 C22_Ch7 C22_Ch8 C35_Ch1 C35_Ch2 C35_Ch3 C35_Ch4 C35_Ch5 C35_Ch6 C35_Ch7 C35_Ch8 C36_Ch1 C36_Ch2 C36_Ch3 C36_Ch4 C36_Ch5 C36_Ch6 C36_Ch7 C36_Ch8: "CAP, CERM, 100 pF, 50 V, +/- 5%, C0G/NP0, 0603", Cap_Case=0603, Manufacturer=MuRata, Supplier Part Number 1=490-1427-1-ND, TempCo=C0G/NP0, Tolerance_%=5, Value1=Unknown, Value2=50V, ValueDisplayed=100pF
C16_Ch1 C16_Ch2 C16_Ch3 C16_Ch4 C16_Ch5 C16_Ch6 C16_Ch7 C16_Ch8 C17_Ch1 C17_Ch2 C17_Ch3 C17_Ch4 C17_Ch5 C17_Ch6 C17_Ch7 C17_Ch8: "CAP, CERM, 0.01 µF, 25 V,+/- 10%, X7R, 0402", Cap_Case=0402, Manufacturer=MuRata, Supplier Part Number 1=490-6043-2-ND, TempCo=X7R, Tolerance_%=10, Value2=25V, ValueDisplayed=0.01µF
C18_Ch1 C18_Ch2 C18_Ch3 C18_Ch4 C18_Ch5 C18_Ch6 C18_Ch7 C18_Ch8 C24_Ch1 C24_Ch2 C24_Ch3 C24_Ch4 C24_Ch5 C24_Ch6 C24_Ch7 C24_Ch8 C31_Ch1 C31_Ch2 C31_Ch3 C31_Ch4 C31_Ch5 C31_Ch6 C31_Ch7 C31_Ch8 C39_Ch1 C39_Ch2 C39_Ch3 C39_Ch4 C39_Ch5 C39_Ch6 C39_Ch7 C39_Ch8 C52_Ch1 C52_Ch2 C52_Ch3 C52_Ch4 C52_Ch5 C52_Ch6 C52_Ch7 C52_Ch8 C69 C74 C75 C78 C79 C90 C95 C96 C99 C100 C124 C125: library part CMP-0007405-4, "CAP, CERM, 1 uF, 25 V, +/- 10%, X7R, 0603", Cap_Case=0603, Manufacturer=MuRata, PartNumber=GRM188R71E105KA12D, Supplier Part Number 1=490-5307-1-ND, TempCo=X7R, Tolerance_%=10%, Value1=Unknown, Value2=25V, ValueDisplayed=1uF
C19_Ch1 C19_Ch2 C19_Ch3 C19_Ch4 C19_Ch5 C19_Ch6 C19_Ch7 C19_Ch8 C32_Ch1 C32_Ch2 C32_Ch3 C32_Ch4 C32_Ch5 C32_Ch6 C32_Ch7 C32_Ch8: "CAP, CERM, 1000 pF, 50 V, +/- 5%, C0G/NP0, 0603", Cap_Case=0603, Manufacturer=MuRata, Supplier Part Number 1=490-1451-1-ND, TempCo=C0G/NP0, Tolerance_%=5, Value1=Unknown, Value2=50V, ValueDisplayed=1000pF
C25_Ch1 C25_Ch2 C25_Ch3 C25_Ch4 C25_Ch5 C25_Ch6 C25_Ch7 C25_Ch8 C26_Ch1 C26_Ch2 C26_Ch3 C26_Ch4 C26_Ch5 C26_Ch6 C26_Ch7 C26_Ch8 C27_Ch1 C27_Ch2 C27_Ch3 C27_Ch4 C27_Ch5 C27_Ch6 C27_Ch7 C27_Ch8 C28_Ch1 C28_Ch2 C28_Ch3 C28_Ch4 C28_Ch5 C28_Ch6 C28_Ch7 C28_Ch8 C48_Ch1 C48_Ch2 C48_Ch3 C48_Ch4 C48_Ch5 C48_Ch6 C48_Ch7 C48_Ch8 C49_Ch1 C49_Ch2 C49_Ch3 C49_Ch4 C49_Ch5 C49_Ch6 C49_Ch7 C49_Ch8 C50_Ch1 C50_Ch2 C50_Ch3 C50_Ch4 C50_Ch5 C50_Ch6 C50_Ch7 C50_Ch8 C51_Ch1 C51_Ch2 C51_Ch3 C51_Ch4 C51_Ch5 C51_Ch6 C51_Ch7 C51_Ch8 C126: "CAP, CERM, 0.01 µF, 25 V,+/- 5%, C0G/NP0, AEC-Q200 Grade 1, 0603", Cap_Case=0603, Manufacturer=Kemet, Supplier Part Number 1=399-14102-1-ND, TempCo=C0G/NP0, Tolerance_%=5, Value2=25V, ValueDisplayed=0.01µF
C37_Ch1 C37_Ch2 C37_Ch3 C37_Ch4 C37_Ch5 C37_Ch6 C37_Ch7 C37_Ch8 C38_Ch1 C38_Ch2 C38_Ch3 C38_Ch4 C38_Ch5 C38_Ch6 C38_Ch7 C38_Ch8: "CAP, CERM, 1000 pF, 25 V,+/- 10%, X7R, 0402", Cap_Case=0402, Manufacturer="Wurth Elektronik", Supplier Part Number 1=710-885012205044, TempCo=X7R, Tolerance_%=10, Value2=25V, ValueDisplayed=1000pF
C41_Ch1 C41_Ch2 C41_Ch3 C41_Ch4 C41_Ch5 C41_Ch6 C41_Ch7 C41_Ch8: "CAP, CERM, 1200 pF, 50 V,+/- 10%, X7R, 0402", Cap_Case=0402, Manufacturer=MuRata, Supplier Part Number 1=490-1304-1-ND, TempCo=X7R, Tolerance_%=10, Value2=50V, ValueDisplayed=1200pF
C42_Ch1 C42_Ch2 C42_Ch3 C42_Ch4 C42_Ch5 C42_Ch6 C42_Ch7 C42_Ch8: "CAP, CERM, 7500 pF, 50 V,+/- 5%, C0G/NP0, 0805", Cap_Case=0805, Manufacturer=MuRata, Supplier Part Number 1=490-1639-1-ND, TempCo=C0G/NP0, Tolerance_%=5, Value2=50V, ValueDisplayed=7500pF
C46_Ch1 C46_Ch2 C46_Ch3 C46_Ch4 C46_Ch5 C46_Ch6 C46_Ch7 C46_Ch8 C55_Ch1 C55_Ch2 C55_Ch3 C55_Ch4 C55_Ch5 C55_Ch6 C55_Ch7 C55_Ch8 C132: "CAP, CERM, 1000 pF, 100 V, +/- 5%, X7R, 0603", Cap_Case=0603, Manufacturer=AVX, Supplier Part Number 1=478-3698-1-ND, TempCo=X7R, Tolerance_%=5, Value1="0.276 ohm", Value2=100V, ValueDisplayed=1000pF
C54_Ch1 C54_Ch2 C54_Ch3 C54_Ch4 C54_Ch5 C54_Ch6 C54_Ch7 C54_Ch8: library part CMP-0006752-5, "CAP, CERM, 0.1 uF, 25 V, +/- 5%, X7R, 0603", Cap_Case=0603, Manufacturer=AVX, PartNumber=06033C104JAT2A, Supplier Part Number 1=478-3713-1-ND, TempCo=X7R, Tolerance_%=5%, Value1="0.05 ohm", Value2=25V
C57 C59: "CAP, CERM, 0.01 µF, 50 V, +/- 5%, C0G/NP0, 0603", Cap_Case=0603, Manufacturer=MuRata, Supplier Part Number 1=490-9666-1-ND, TempCo=C0G/NP0, Tolerance_%=5, Value1=Unknown, Value2=50V, ValueDisplayed=0.01µF
C60 C61 C63 C65 C66 C67 C68 C71 C81 C82 C84 C86 C87 C88 C89 C92: "CAP, CERM, 10 pF, 50 V,+/- 5%, C0G/NP0, AEC-Q200 Grade 1, 0402", Cap_Case=0402, Manufacturer=TDK, Supplier Part Number 1=445-5584-1-ND, TempCo=C0G/NP0, Tolerance_%=5, Value2=50V, ValueDisplayed=10pF
C72 C93: library part CMP-0006761-4, "CAP, CERM, 10 pF, 50 V, +/- 5%, C0G/NP0, 0603", Cap_Case=0603, Manufacturer=AVX, PartNumber=06035A100JAT2A, Supplier Part Number 1=478-1163-1-ND, TempCo=C0G/NP0, Tolerance_%=5%, Value1="0.403 ohm", Value2=50V, ValueDisplayed=10pF
C102 C103 C105 C108 C140 C141: library part CMP-0006867-1, "CAP, CERM, 1 uF, 25 V, +/- 10%, X7R, 0603", Cap_Case=0603, Manufacturer=Kemet, Supplier Part Number 1=399-7376-1-ND, TempCo=X7R, Tolerance_%=10%, Value1=Unknown, Value2=25V, ValueDisplayed=1uF
C104 C106 C107: "CAP, CERM, 10 µF, 16 V, +/- 20%, X7R, 0805", Cap_Case=0805, Manufacturer="Taiyo Yuden", Supplier Part Number 1=587-3319-1-ND, TempCo=X7R, Tolerance_%=20, Value1=Unknown, Value2=16V, ValueDisplayed=10µF
C109: "CAP, AL, 22 µF, 100 V, +/- 20%, 0.55 ohm, SMD", Cap_Case=JA0, Manufacturer=Chemi-Con, Supplier Part Number 1=565-2341-1-ND, Tolerance_%=20, Value1="0.55 ohm", Value2=100V, ValueDisplayed=22µF
C110: "CAP, CERM, 10 µF, 100 V, +/- 20%, X7S,", Cap_Case=2220, Manufacturer=TDK, Supplier Part Number 1=445-5212-1-ND, TempCo=X7S, Tolerance_%=20, Value1="0.005 ohm", Value2=100V, ValueDisplayed=10µF
C111: "CAP, CERM, 0.1 µF, 100 V, +/- 10%, X7R, 0805", Cap_Case=0805, Manufacturer=TDK, Supplier Part Number 1=445-1418-1-ND, TempCo=X7R, Tolerance_%=10, Value1="0.0158 ohm", Value2=100V, ValueDisplayed=0.1µF
C112 C116: "CAP, CERM, 0.1 µF, 100 V, +/- 10%, X7R, 0603", Cap_Case=0603, Manufacturer=MuRata, Supplier Part Number 1=490-3285-1-ND, TempCo=X7R, Tolerance_%=10, Value1=Unknown, Value2=100V, ValueDisplayed=0.1µF
C113: "CAP, Aluminum Polymer, 180 µF, 16 V, +/- 20%, 0.016 ohm, HC0 SMD", Cap_Case=HC0, Manufacturer=Chemi-Con, Supplier Part Number 1=565-3078-1-ND, Tolerance_%=20, Value1="0.016 ohm", Value2=16V, ValueDisplayed=180µF
C114: "CAP, CERM, 2.2 µF, 16 V, +/- 10%, X7R, 0805", Cap_Case=0805, Manufacturer=TDK, Supplier Part Number 1=445-1420-1-ND, TempCo=X7R, Tolerance_%=10, Value1="0.0049 ohm", Value2=16V, ValueDisplayed=2.2µF
C115: "CAP, CERM, 1500 pF, 100 V, +/- 5%, C0G/NP0, 0603", Cap_Case=0603, Manufacturer=MuRata, Supplier Part Number 1=GRM1885C2A152JA01D-ND, TempCo=C0G/NP0, Tolerance_%=5, Value1=Unknown, Value2=100V, ValueDisplayed=1500pF
C117: "CAP, CERM, 330 pF, 100 V, +/- 5%, C0G/NP0, 0603", Cap_Case=0603, Manufacturer=TDK, Supplier Part Number 1=445-2309-1-ND, TempCo=C0G/NP0, Tolerance_%=5, Value1="0.1269 ohm", Value2=100V, ValueDisplayed=330pF
C118 C119 C133: "CAP, CERM, 1 µF, 25 V, +/- 10%, X7R, 0603", Cap_Case=0603, Manufacturer=MuRata, Supplier Part Number 1=490-5307-1-ND, TempCo=X7R, Tolerance_%=10, Value1=Unknown, Value2=25V, ValueDisplayed=1µF
C120: "CAP, CERM, 0.056 µF, 50 V, +/- 10%, X7R, 0603", Cap_Case=0603, Manufacturer=MuRata, Supplier Part Number 1=81-GRM188R71H563KA93, TempCo=X7R, Tolerance_%=10, Value1=Unknown, Value2=50V, ValueDisplayed=0.056µF
C121: "CAP, CERM, 0.1 µF, 100 V, +/- 10%, X7R, 0805", Cap_Case=0805, Manufacturer=TDK, Supplier Part Number 1=445-1418-1-ND, TempCo=X7R, Tolerance_%=10, Value1="0.020726 ohm", Value2=100V, ValueDisplayed=0.1µF
C129 C130: library part CMP-0007891-2, "CAP, CERM, 1 uF, 100 V, +/- 10%, X7S, 0805", Cap_Case=0805, Manufacturer=TDK, PartNumber=C2012X7S2A105K125AB, Supplier Part Number 1=445-5205-1-ND, TempCo=X7S, Tolerance_%=10%, Value1="0.008255 ohm", Value2=100V, ValueDisplayed=1uF
C131 C134 C165: "CAP, CERM, 0.01 µF, 100 V, +/- 10%, X7R, 0603", Cap_Case=0603, Manufacturer=AVX, Supplier Part Number 1=478-1205-1-ND, TempCo=X7R, Tolerance_%=10, Value1="0.098 ohm", Value2=100V, ValueDisplayed=0.01µF
C137: library part CMP-0009120-1, "CAP, CERM, 10 uF, 50 V, +/- 20%, X7R, 1210", Cap_Case=1210, Manufacturer=TDK, Supplier Part Number 1=445-14933-1-ND, TempCo=X7R, Tolerance_%=20%, Value1=Unknown, Value2=50V, ValueDisplayed=10uF
C139 C163: "CAP, CERM, 10 µF, 25 V,+/- 20%, X5R, 0603", Cap_Case=0603, Manufacturer=MuRata, Supplier Part Number 1=490-7202-1-ND, TempCo=X5R, Tolerance_%=20, Value2=25V, ValueDisplayed=10µF
C152 C153 C154: "CAP, CERM, 22 µF, 16 V, +/- 20%, X7R, 1206_190", Cap_Case=1206, Manufacturer="Taiyo Yuden", Supplier Part Number 1=587-4319-1-ND, TempCo=X7R, Tolerance_%=20, Value1=Unknown, Value2=16V, ValueDisplayed=22µF
C155: "CAP, CERM, 2.2 µF, 16 V, +/- 10%, X7R, 0603", Cap_Case=0603, Manufacturer="Taiyo Yuden", Supplier Part Number 1=EMK107BB7225KA-T-ND, TempCo=X7R, Tolerance_%=10, Value1=Unknown, Value2=16V, ValueDisplayed=2.2µF
C156: "CAP, TA, 47 µF, 16 V, +/- 20%, 0.6 ohm, SMD", Cap_Case=F95_B, Manufacturer=AVX, Supplier Part Number 1=478-8478-1-ND, Tolerance_%=20, Value1="0.6 ohm", Value2=16V, ValueDisplayed=47µF
C157 C158: "CAP, CERM, 4.7 µF, 25 V,+/- 10%, X5R, 1206", Cap_Case=1206, Manufacturer=MuRata, Supplier Part Number 1=490-3372-1-ND, TempCo=X5R, Tolerance_%=10, Value1="0.006 ohm", Value2=25V, ValueDisplayed=4.7µF
C159: "CAP, CERM, 1 µF, 16 V,+/- 10%, X5R, 0402", Cap_Case=0402, Manufacturer=TDK, Supplier Part Number 1=445-4978-1-ND, TempCo=X5R, Tolerance_%=10, Value2=16V, ValueDisplayed=1µF
C160 C161 C162: "CAP, CERM, 22 µF, 10 V, +/- 20%, X7S, 0805", Cap_Case=0805, Manufacturer=TDK, Supplier Part Number 1=445-14560-1-ND, TempCo=X7S, Tolerance_%=20, Value1=Unknown, Value2=10V, ValueDisplayed=22µF
C164: "CAP, CERM, 0.22 µF, 16 V,+/- 10%, X7R, 0402", Cap_Case=0402, Manufacturer=MuRata, Supplier Part Number 1=490-5418-1-ND, TempCo=X7R, Tolerance_%=10, Value2=16V, ValueDisplayed=0.22µF
CS+1_Ch1 CS+1_Ch2 CS+1_Ch3 CS+1_Ch4 CS+1_Ch5 CS+1_Ch6 CS+1_Ch7 CS+1_Ch8 CS-1_Ch1 CS-1_Ch2 CS-1_Ch3 CS-1_Ch4 CS-1_Ch5 CS-1_Ch6 CS-1_Ch7 CS-1_Ch8: library part CMP-0078143-2, "TEST POINT.  No entry in BOM.", Manufacturer=N/A
D1_Ch1 D1_Ch2 D1_Ch3 D1_Ch4 D1_Ch5 D1_Ch6 D1_Ch7 D1_Ch8 D3_Ch1 D3_Ch2 D3_Ch3 D3_Ch4 D3_Ch5 D3_Ch6 D3_Ch7 D3_Ch8 D4_Ch1 D4_Ch2 D4_Ch3 D4_Ch4 D4_Ch5 D4_Ch6 D4_Ch7 D4_Ch8 D7: "Diode, Schottky, 40V, 0.25A, SOD-523", Manufacturer="ON Semiconductor", Supplier Part Number 1=NSR0240V2T1GOSCT-ND, Value1=0.25A, Value2=0.7V
D2_Ch1 D2_Ch2 D2_Ch3 D2_Ch4 D2_Ch5 D2_Ch6 D2_Ch7 D2_Ch8: library part VS-20WT04FN, "Diode FERD (Field Effect Rectifier Diode) 100V 20A Surface Mount DPAK", Manufacturer=STMicroelectronics, Supplier Part Number 1=497-16946-2-ND, Value1=20A, Value2=0.53V
D5 D6: library part CMP-0029001-1, "Diode, Ultrafast, 100 V, 0.15 A, SOD-123", Manufacturer="Diodes Inc.", Supplier Part Number 1=1N4148W-FDICT-ND, Value1=0.15A, Value2=1.25V
D8: "Diode, TVS, Uni, 18 V, 29.2 Vc, SMA", Manufacturer=Littelfuse, Power_W=3.3, Supplier Part Number 1=SMAJ18ALFCT-ND, Value1=3.3W
D9: "Diode, Schottky, 30 V, 5 A, SMC", Manufacturer="Diodes Inc.", Supplier Part Number 1=B530C-FDICT-ND, Value1=5A, Value2=0.55V
D10: "Diode, Schottky, 100 V, 5 A, SMC", Manufacturer="Comchip Technology", Supplier Part Number 1=641-1124-1-ND, Value1=5A, Value2=0.85V
D11 D13 D14 D15 D17 D18 D33: "LED, Green, SMD", Color=green, Manufacturer="Wurth Elektronik", Supplier Part Number 1=732-4980-1-ND, Value1=W, Value2=2V
D12 D16 D19 D20 D21 D22 D23 D24 D25 D26 D27 D28 D29 D30 D31 D32: library part CMP-0005801-3, "Diode, Zener, 4.7 V, 500 mW, SOD-123", Manufacturer="Diodes Inc.", Power_W=500mW, Value1=0.5W
F1_Ch1 F1_Ch2 F1_Ch3 F1_Ch4 F1_Ch5 F1_Ch6 F1_Ch7 F1_Ch8: "Fuse, 15 A, SMD", Irating_A=15, Manufacturer="Cooper Bussman", Supplier Part Number 1=283-2532-1-ND
FID1 FID2 FID3 FID4 FID5 FID6: "Fiducial mark.  There is nothing to buy or mount.", Manufacturer=N/A
H1 H2 H3 H4 H5 H6 H13 H14 H17: "Machine Screw, Round, #4-40 x 1/4, Nylon, Philips panhead", Alternate Manufacturer=-, DigiKeyPartNumber=H542-ND, Manufacturer="B&F Fastener Supply"
H7 H8 H9 H10 H11 H12 H15 H16 H18: "Standoff, Hex, 1\"L #4-40 Aluminum", Manufacturer=Keystone, Supplier Part Number 1=2205K-ND
J1_Ch1 J1_Ch2 J1_Ch3 J1_Ch4 J1_Ch5 J1_Ch6 J1_Ch7 J1_Ch8 J3_Ch1 J3_Ch2 J3_Ch3 J3_Ch4 J3_Ch5 J3_Ch6 J3_Ch7 J3_Ch8: library part CMP-0087889-1, "Terminal Connector Rectangular Lug, Grounding 10-14 AWG 1/8 Stud", Current_A=25A, Manufacturer=Panduit, Voltage_V=600V
J2_Ch1 J2_Ch2 J2_Ch3 J2_Ch4 J2_Ch5 J2_Ch6 J2_Ch7 J2_Ch8: "Header (Shrouded), 2.5mm, 2x1, Tin, TH", Color=White, Current_A=3, Manufacturer="JST Manufacturing", Supplier Part Number 1=455-1611-ND, Voltage_V=250
J4: "Header, 2.54mm, 3x1, Tin, TH", Color=Black, Current_A=4, Manufacturer=Molex, Supplier Part Number 1=WM50016-03-ND, Voltage_V=250
J5: library part CMP-0003814-2, "C2000 controlCARD-120HSEC connector, SMT", Manufacturer=Samtec
J6: library part CMP-0003859-2, "C2000 controlCARD-180HSEC (60-pin addon) connector, SMT", Manufacturer=Samtec
L1_Ch1 L1_Ch2 L1_Ch3 L1_Ch4 L1_Ch5 L1_Ch6 L1_Ch7 L1_Ch8: library part CMP-0064071-1, "Inductor, Shielded Drum Core, Powdered Iron, 1 uH, 5 A, 0.022 ohm, SMD", Manufacturer="Wurth Elektronik", Supplier Part Number 1=732-3342-1-ND, Value1="0.022 ohm", Value2=5A, ValueDisplayed=1uH
L2_Ch1 L2_Ch2 L2_Ch3 L2_Ch4 L2_Ch5 L2_Ch6 L2_Ch7 L2_Ch8: library part CMP-0085394-1, "Inductor, Shielded, Mn-Zn, 47 µH, 13 A, 0.00968 ohm, SMD", Manufacturer="Wurth Elektronik", Value1="0.00968 ohm", Value2=13A, ValueDisplayed=47µH
L3: "Inductor, Shielded Drum Core, Ferrite, 47 µH, 2.9 A, 0.07 ohm, SMD", Manufacturer=Coilcraft, Value1="0.07 ohm", Value2=2.9A, ValueDisplayed=47µH
L4: library part CMP-0003369-1, "Ferrite Bead, 1000 ohm @ 100 MHz, 1.5 A, 1806", Manufacturer=MuRata, Supplier Part Number 1=490-1061-1-ND, Value1="0.09 ohm", Value2=1.5A, ValueDisplayed="1000 ohm"
L5: library part CMP-0059761-1, "Inductor, Wirewound, 4.7 uH, 0.95 A, 0.38 ohm, SMD", Manufacturer="Taiyo Yuden", Supplier Part Number 1=963-MAKK2016T4R7M, Value1="0.38 ohm", Value2=0.95A, ValueDisplayed=4.7uH
L6: "Inductor, Shielded, Composite, 4.7 µH, 2.7 A, 0.05 ohm, SMD", Manufacturer=Coilcraft, Supplier Part Number 1=994-XFL4020-472MEB, Value1="0.05 ohm", Value2=2.7A, ValueDisplayed=4.7µH
LBL1: library part CMP-0003625-1, "Thermal Transfer Printable Labels, 0.650\" W x 0.200\" H - 10,000 per roll", Manufacturer=Brady, Supplier Part Number 1=97C5133
Logo1: library part CMP-0074844-1
Logo3: library part CMP-0074847-1, "FCC_disclaimer"
Logo4: library part CMP-0074769-1
LOGO5: library part CMP-0074837-1, "IEC 61010-1 Hot Surface Warning"
Logo6: library part Pb-Free
Logo7: library part ESD_Susceptible, "ESD Susceptible Symbol"
NT1: "Single point connection between nets."
Q1_Ch1 Q1_Ch2 Q1_Ch3 Q1_Ch4 Q1_Ch5 Q1_Ch6 Q1_Ch7 Q1_Ch8 Q7_Ch1 Q7_Ch2 Q7_Ch3 Q7_Ch4 Q7_Ch5 Q7_Ch6 Q7_Ch7 Q7_Ch8: library part CMP-0000708-1, "MOSFET, N-CH, 40 V, 15 A, DQJ0008A (VSONP-8)", Alternate Manufacturer=None, Manufacturer="Texas Instruments", Supplier Part Number 1=296-30572-1-ND, Value1=0.009, Value2="7.7 nC"
Q2 Q3: "MOSFET, N-CH, 25 V, 100 A, DNK0008A (VSON-CLIP-8)", Alternate Manufacturer=None, Manufacturer="Texas Instruments", Supplier Part Number 1=CSD16570Q5B-ND, Value1="0.0008 ohm", Value2="192 nC"
Q4: library part CMP-0000416-1, "Transistor, NPN, 80 V, 0.5 A, SOT-23", Manufacturer="Diodes Inc.", Supplier Part Number 1=MMBTA06-FDICT-ND, Value1="0.5 A"
Q5 Q6: "MOSFET, N-CH, 100 V, 21 A, PowerPAK SO-8", Alternate Manufacturer=None, Manufacturer=Vishay-Siliconix, Supplier Part Number 1=SI7454DDP-T1-GE3CT-ND, Value1="0.047 ohm", Value2="12.8 nC"
R1_Ch1 R1_Ch2 R1_Ch3 R1_Ch4 R1_Ch5 R1_Ch6 R1_Ch7 R1_Ch8 R5_Ch1 R5_Ch2 R5_Ch3 R5_Ch4 R5_Ch5 R5_Ch6 R5_Ch7 R5_Ch8 R18_Ch1 R18_Ch2 R18_Ch3 R18_Ch4 R18_Ch5 R18_Ch6 R18_Ch7 R18_Ch8 R24_Ch1 R24_Ch2 R24_Ch3 R24_Ch4 R24_Ch5 R24_Ch6 R24_Ch7 R24_Ch8 R173_Ch1 R173_Ch2 R173_Ch3 R173_Ch4 R173_Ch5 R173_Ch6 R173_Ch7 R173_Ch8 R174_Ch1 R174_Ch2 R174_Ch3 R174_Ch4 R174_Ch5 R174_Ch6 R174_Ch7 R174_Ch8 R190 R191 R194 R195: library part CMP-0022746-5, "RES, 10.0 k, 1%, 0.1 W, 0603", Manufacturer=Yageo, Power_W=100mW, Supplier Part Number 1=311-10.0KHRCT-ND, TempCo="100 ppm/C", Tolerance_%=1%, Value2=0.1W, Value_Code=10k0, ValueDisplayed=10.0k
R2_Ch1 R2_Ch2 R2_Ch3 R2_Ch4 R2_Ch5 R2_Ch6 R2_Ch7 R2_Ch8 R3_Ch1 R3_Ch2 R3_Ch3 R3_Ch4 R3_Ch5 R3_Ch6 R3_Ch7 R3_Ch8 R8_Ch1 R8_Ch2 R8_Ch3 R8_Ch4 R8_Ch5 R8_Ch6 R8_Ch7 R8_Ch8 R172_Ch1 R172_Ch2 R172_Ch3 R172_Ch4 R172_Ch5 R172_Ch6 R172_Ch7 R172_Ch8 R216_Ch1 R216_Ch2 R216_Ch3 R216_Ch4 R216_Ch5 R216_Ch6 R216_Ch7 R216_Ch8 R217_Ch1 R217_Ch2 R217_Ch3 R217_Ch4 R217_Ch5 R217_Ch6 R217_Ch7 R217_Ch8 R220_Ch1 R220_Ch2 R220_Ch3 R220_Ch4 R220_Ch5 R220_Ch6 R220_Ch7 R220_Ch8: "RES, 0, 5%, 0.1 W, 0603", Manufacturer="Yageo America", Power_W=0.1, Supplier Part Number 1=311-0.0GRCT-ND, TempCo="200 ppm/C", Tolerance_%=5, Value1=5%, Value2=0.1W, Value_Code=0000, ValueDisplayed=0
R4_Ch1 R4_Ch2 R4_Ch3 R4_Ch4 R4_Ch5 R4_Ch6 R4_Ch7 R4_Ch8: "RES, 10.0, 1%, 0.25 W, 1206", Manufacturer="Yageo America", Power_W=0.25, Supplier Part Number 1=311-10.0FRCT-ND, TempCo="200 ppm/C", Tolerance_%=1, Value1=1%, Value2=0.25W, Value_Code=10R0, ValueDisplayed=DNP
R6_Ch1 R6_Ch2 R6_Ch3 R6_Ch4 R6_Ch5 R6_Ch6 R6_Ch7 R6_Ch8 R7_Ch1 R7_Ch2 R7_Ch3 R7_Ch4 R7_Ch5 R7_Ch6 R7_Ch7 R7_Ch8: library part Y14880R01000B9R, "Current Sense Resistors - SMD 0.005ohms 0.1% 3w", Manufacturer="Vishay Foil Resistors", Power_W=3, TempCo="15 ppm/C", Tolerance_%=0.1, Value1=0.1%, Value2=3W, Value_Code=R010, ValueDisplayed=5mOhm
R9_Ch1 R9_Ch2 R9_Ch3 R9_Ch4 R9_Ch5 R9_Ch6 R9_Ch7 R9_Ch8: "RES, 10.0, 1%, 0.25 W, 1206", Manufacturer="Yageo America", Power_W=0.25, Supplier Part Number 1=311-10.0FRCT-ND, TempCo="200 ppm/C", Tolerance_%=1, Value1=1%, Value2=0.25W, Value_Code=10R0, ValueDisplayed=10.0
